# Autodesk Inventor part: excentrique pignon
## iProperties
Shininess: 20.0
Angle Display Precision: 2
Document Length Units: 11269
Document Angle Units: 11279
Document Time Units: 11290
Document Mass Units: 11283
Document Length Units Precision: 3
Document Angle Units Precision: 2
Compacted: True
Created: 2009-07
Part Number: excentrique pignon
Material: Par défaut
Document SubType Name: Modélisation
Designer: EL
Density: 1 g/cm^3
Density: 0.0
Volumn: 0.0
Area: 0.0
PropertySet Name: Model Information
Control State: 0
Master: False
Checked Out: False
Author: EL
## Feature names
1. Extrusion1
2. Extrusion3
3. Extrusion4
4. Extrusion6
5. Révolution1 [Revolution]
